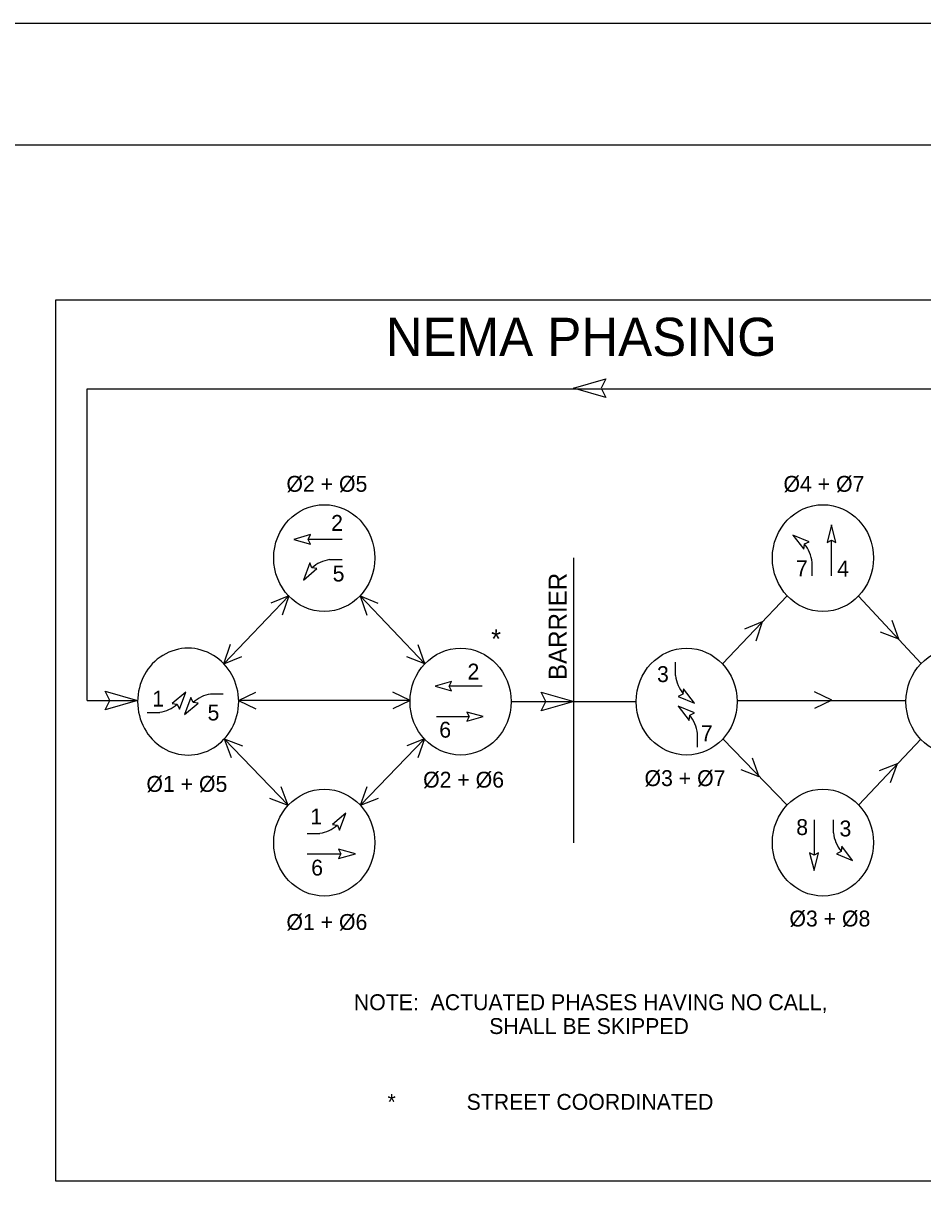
# Model space of a CAD drawing. Extents: x 0 to 3.01, y -0.05 to 1.83.
# Drawn here: x 0.74 to 1.168, y 1.274 to 1.833 of the extents above; entities that cross this region are included whole.
import ezdxf

# ---------------------------------------------------------------- set-up
doc = ezdxf.new("R2010")
doc.units = 0
for name, color, linetype in [('RD_SHT_IplotShp', 7, 'Continuous'), ('TR_TS_Border', 7, 'Continuous'), ('TR_TS_Phase1', 7, 'Continuous'), ('TR_TS_Phase2', 7, 'Continuous'), ('TR_TS_Phase3', 7, 'Continuous'), ('TR_TS_Phase5', 7, 'Continuous'), ('TR_TS_Phase6', 7, 'Continuous'), ('TR_TS_Phase7', 7, 'Continuous')]:
    doc.layers.add(name, color=color, linetype=linetype)

msp = doc.modelspace()

# ---------------------------------------------------------------- linework, layer by layer
at = {"layer": 'RD_SHT_IplotShp'}
msp.add_lwpolyline([(0, 0), (3, 0), (3, 1.83333), (0, 1.83333)], close=True, dxfattribs=at)
at = {"layer": 'TR_TS_Border'}
for p, q in [((2.94187, 1.83333), (0.031, 1.83333)), ((2.96235, 1.7754), (0.16861, 1.7754)), ((1.00185, 1.65988), (1.01734, 1.66431)), ((1.01734, 1.66431), (1.01512, 1.65988)), ((0.7706, 1.6596), (1.24441, 1.6596)), ((0.7706, 1.51138), (0.7706, 1.6596)), ((1.01734, 1.65546), (1.00185, 1.65988)), ((1.01512, 1.65988), (1.01734, 1.65546)), ((1.00203, 1.44362), (1.00203, 1.57914)), ((0.83567, 1.52879), (0.86647, 1.56116)), ((0.86647, 1.56116), (0.85801, 1.55768)), ((0.86647, 1.56116), (0.86335, 1.55184)), ((0.90047, 1.56116), (0.93127, 1.52879)), ((0.90047, 1.56116), (0.90893, 1.55768)), ((0.90047, 1.56116), (0.90358, 1.55184)), ((1.07271, 1.52879), (1.10351, 1.56116)), ((1.13742, 1.56097), (1.16715, 1.52897)), ((1.09167, 1.54874), (1.08321, 1.54526)), ((1.09167, 1.54874), (1.08855, 1.53951)), ((1.15656, 1.54046), (1.15335, 1.5494)), ((1.15656, 1.54046), (1.14792, 1.54384)), ((0.83567, 1.52879), (0.83878, 1.5381)), ((0.93127, 1.52879), (0.92806, 1.53773)), ((0.83567, 1.52879), (0.84412, 1.53227)), ((0.93127, 1.52879), (0.92272, 1.53217)), ((0.78137, 1.51138), (0.77915, 1.5158)), ((0.77915, 1.5158), (0.79463, 1.51138)), ((0.84261, 1.51138), (0.85089, 1.51533)), ((0.92424, 1.51138), (0.91596, 1.51533)), ((0.98877, 1.51091), (0.98654, 1.51533)), ((0.98654, 1.51533), (1.00203, 1.51091)), ((1.12469, 1.51147), (1.1165, 1.51542)), ((0.7706, 1.51138), (0.79463, 1.51138)), ((0.77915, 1.50695), (0.78137, 1.51138)), ((0.79463, 1.51138), (0.77915, 1.50695)), ((0.92424, 1.51138), (0.84261, 1.51138)), ((0.84261, 1.51138), (0.85089, 1.50742)), ((0.92424, 1.51138), (0.91596, 1.50742)), ((0.9723, 1.51091), (1.03167, 1.51091)), ((0.98654, 1.50648), (0.98877, 1.51091)), ((1.00203, 1.51091), (0.98654, 1.50648)), ((1.07974, 1.51138), (1.16003, 1.51138)), ((1.12469, 1.51147), (1.1165, 1.50752)), ((0.86629, 1.46159), (0.83585, 1.49312)), ((0.83585, 1.49312), (0.83905, 1.48427)), ((0.83585, 1.49312), (0.84448, 1.48982)), ((0.93109, 1.49312), (0.90056, 1.46159)), ((0.93109, 1.49312), (0.92263, 1.48982)), ((0.93109, 1.49312), (0.92788, 1.48408)), ((1.10342, 1.46159), (1.07289, 1.49312)), ((1.16706, 1.49293), (1.13751, 1.46178)), ((1.09024, 1.47505), (1.08695, 1.48389)), ((1.09024, 1.47505), (1.08161, 1.47834)), ((1.15576, 1.48117), (1.14721, 1.47787)), ((1.15576, 1.48117), (1.15255, 1.47213)), ((0.86615, 1.46143), (0.86294, 1.47027)), ((0.90056, 1.46159), (0.90376, 1.47044)), ((0.86615, 1.46143), (0.85751, 1.46472)), ((0.90056, 1.46159), (0.90919, 1.46488))]:
    msp.add_line(p, q, dxfattribs=at)
msp.add_lwpolyline([(0.75574, 1.70195), (1.26043, 1.70195), (1.26043, 1.28268), (0.75574, 1.28268)], close=True, dxfattribs=at)
for centre in [(0.88338, 1.57906), (1.1205, 1.57906), (0.94819, 1.51079), (1.0557, 1.51079), (1.18403, 1.51079), (0.88338, 1.44371), (1.1205, 1.44371)]:
    msp.add_ellipse(centre, major_axis=(0, 0.02541), ratio=0.945811, dxfattribs=at)
for start_param, end_param in [(4.712389, 7.853982), (1.570796, 4.712389)]:
    msp.add_ellipse((0.81865, 1.51079), major_axis=(0, 0.02541), ratio=0.945811, start_param=start_param, end_param=end_param, dxfattribs=at)
at = {"layer": 'TR_TS_Phase1'}
for p, q in [((0.79911, 1.50564), (0.80515, 1.50564)), ((0.87527, 1.44812), (0.88132, 1.44812)), ((0.87527, 1.43843), (0.8913, 1.43843))]:
    msp.add_line(p, q, dxfattribs=at)
for points in [[(0.81335, 1.50953), (0.81349, 1.50951), (0.8145, 1.50719), (0.81752, 1.51532), (0.81111, 1.5099), (0.81335, 1.50953)], [(0.88951, 1.45201), (0.88965, 1.45199), (0.89066, 1.44966), (0.89368, 1.4578), (0.88727, 1.45238), (0.88951, 1.45201)], [(0.8902, 1.43621), (0.89817, 1.43843), (0.8902, 1.44066), (0.8913, 1.43843), (0.8902, 1.43621)]]:
    msp.add_lwpolyline(points, dxfattribs=at)
for centre, end_param in [((0.8031, 1.52239), 0.700777), ((0.87924, 1.46486), 0.701762)]:
    msp.add_ellipse(centre, major_axis=(0, -0.01682), ratio=0.945811, start_param=0.132601, end_param=end_param, dxfattribs=at)
at = {"layer": 'TR_TS_Phase2'}
msp.add_line((0.95846, 1.51816), (0.94279, 1.51816), dxfattribs=at)
msp.add_lwpolyline([(0.94386, 1.52032), (0.93612, 1.51816), (0.94386, 1.51599), (0.94279, 1.51816), (0.94386, 1.52032)], dxfattribs=at)
at = {"layer": 'TR_TS_Phase3'}
for p, q in [((1.05025, 1.52954), (1.05025, 1.52315)), ((1.11628, 1.45464), (1.11628, 1.43769)), ((1.12543, 1.45464), (1.12543, 1.44834))]:
    msp.add_line(p, q, dxfattribs=at)
for points in [[(1.05395, 1.51459), (1.05391, 1.51434), (1.05171, 1.51327), (1.0594, 1.51008), (1.05428, 1.51685), (1.05395, 1.51459)], [(1.11417, 1.43885), (1.11628, 1.43043), (1.11838, 1.43885), (1.11628, 1.43769), (1.11417, 1.43885)], [(1.12912, 1.43969), (1.1291, 1.43953), (1.1269, 1.43847), (1.13459, 1.43527), (1.12946, 1.44205), (1.12912, 1.43969)]]:
    msp.add_lwpolyline(points, dxfattribs=at)
for centre, end_param in [((1.0661, 1.52545), 5.427381), ((1.14123, 1.4506), 5.417976)]:
    msp.add_ellipse(centre, major_axis=(0, -0.01682), ratio=0.945811, start_param=4.84499, end_param=end_param, dxfattribs=at)
at = {"layer": 'TR_TS_Phase5'}
for p, q in [((0.89185, 1.58798), (0.87574, 1.58798)), ((0.89185, 1.5783), (0.88581, 1.5783)), ((0.83538, 1.51428), (0.82934, 1.51428))]:
    msp.add_line(p, q, dxfattribs=at)
for points in [[(0.87683, 1.59021), (0.86887, 1.58798), (0.87683, 1.58575), (0.87574, 1.58798), (0.87683, 1.59021)], [(0.87758, 1.57441), (0.87748, 1.57442), (0.87647, 1.57675), (0.87345, 1.56861), (0.87986, 1.57404), (0.87758, 1.57441)], [(0.82107, 1.51039), (0.821, 1.51041), (0.82, 1.51273), (0.81697, 1.5046), (0.82338, 1.51002), (0.82107, 1.51039)]]:
    msp.add_lwpolyline(points, dxfattribs=at)
for centre, end_param in [((0.88797, 1.56166), 0.715547), ((0.83151, 1.4977), 0.719657)]:
    msp.add_ellipse(centre, major_axis=(0, 0.01682), ratio=0.945811, start_param=0.132601, end_param=end_param, dxfattribs=at)
at = {"layer": 'TR_TS_Phase6'}
msp.add_line((0.93674, 1.50367), (0.95232, 1.50367), dxfattribs=at)
msp.add_lwpolyline([(0.95125, 1.5015), (0.95899, 1.50367), (0.95125, 1.50583), (0.95232, 1.50367), (0.95125, 1.5015)], dxfattribs=at)
at = {"layer": 'TR_TS_Phase7'}
for p, q in [((1.12455, 1.57066), (1.12455, 1.5876)), ((1.11539, 1.57066), (1.11539, 1.57695)), ((1.06078, 1.48916), (1.06078, 1.49555))]:
    msp.add_line(p, q, dxfattribs=at)
for points in [[(1.11175, 1.58577), (1.11392, 1.58682), (1.10623, 1.59002), (1.11136, 1.58324), (1.11172, 1.58576), (1.11175, 1.58577)], [(1.12665, 1.58644), (1.12455, 1.59486), (1.12244, 1.58644), (1.12455, 1.5876), (1.12665, 1.58644)], [(1.0572, 1.50431), (1.05721, 1.50436), (1.0594, 1.50543), (1.05171, 1.50862), (1.05684, 1.50185), (1.0572, 1.50431)]]:
    msp.add_lwpolyline(points, dxfattribs=at)
for centre, end_param in [((1.09967, 1.57482), 5.421194), ((1.04511, 1.49338), 5.422668)]:
    msp.add_ellipse(centre, major_axis=(0, 0.01682), ratio=0.945811, start_param=4.84499, end_param=end_param, dxfattribs=at)

# ---------------------------------------------------------------- texts
at = {"layer": 'TR_TS_Border'}
for s, height, p in [('NEMA PHASING', 0.0181389, (0.91262, 1.67525)), ('Ø2 + Ø5', 0.007558, (0.86539, 1.61061)), ('Ø4 + Ø7', 0.007558, (1.10174, 1.61061)), ('*', 0.00907, (0.96272, 1.53612)), ('Ø3 + Ø7', 0.007558, (1.03567, 1.47062)), ('Ø1 + Ø5', 0.007558, (0.79881, 1.46788)), ('Ø2 + Ø6', 0.007558, (0.93039, 1.46989)), ('Ø3 + Ø8', 0.007558, (1.10457, 1.40384)), ('Ø1 + Ø6', 0.007558, (0.86539, 1.4022)), ('NOTE:  ACTUATED PHASES HAVING NO CALL,', 0.0075579, (0.89745, 1.36403)), ('SHALL BE SKIPPED', 0.0075579, (0.96182, 1.35269)), ('*            STREET COORDINATED', 0.0075579, (0.91345, 1.31663))]:
    msp.add_text(s, height=height, dxfattribs=at).set_placement(p)
msp.add_text('BARRIER', height=0.008578, rotation=90, dxfattribs=at).set_placement((0.99867, 1.52107))
at = {"layer": 'TR_TS_Phase1'}
for s, p in [('1', (0.80158, 1.50845)), ('1', (0.87673, 1.45237)), ('6', (0.87717, 1.42805))]:
    msp.add_text(s, height=0.00756, dxfattribs=at).set_placement(p)
at = {"layer": 'TR_TS_Phase2'}
msp.add_text('2', height=0.00756, dxfattribs=at).set_placement((0.95147, 1.52129))
at = {"layer": 'TR_TS_Phase3'}
for s, p in [('3', (1.0416, 1.52009)), ('8', (1.10781, 1.44734)), ('3', (1.12838, 1.44667))]:
    msp.add_text(s, height=0.00756, dxfattribs=at).set_placement(p)
at = {"layer": 'TR_TS_Phase5'}
for s, p in [('2', (0.88664, 1.59202)), ('5', (0.88736, 1.56795)), ('5', (0.82788, 1.50184))]:
    msp.add_text(s, height=0.00756, dxfattribs=at).set_placement(p)
at = {"layer": 'TR_TS_Phase6'}
msp.add_text('6', height=0.00756, dxfattribs=at).set_placement((0.93807, 1.49365))
at = {"layer": 'TR_TS_Phase7'}
for s, p in [('7', (1.10765, 1.57043)), ('4', (1.12726, 1.57028)), ('7', (1.06243, 1.49196))]:
    msp.add_text(s, height=0.00756, dxfattribs=at).set_placement(p)

doc.saveas('drawing.dxf')
